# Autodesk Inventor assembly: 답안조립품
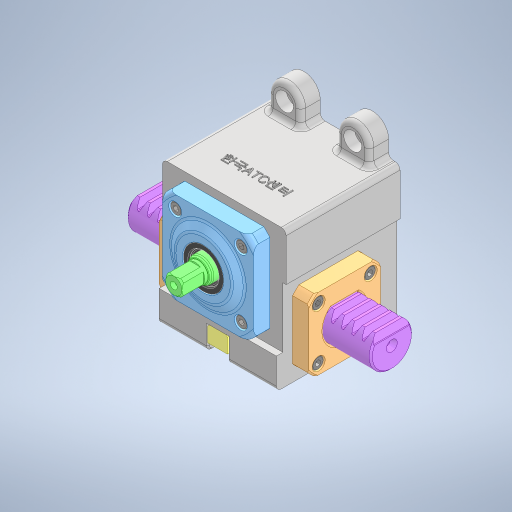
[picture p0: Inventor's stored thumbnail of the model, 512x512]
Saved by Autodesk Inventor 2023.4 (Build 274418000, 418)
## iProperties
Created: 2024-11
Part Number: 답안조립품
Document SubType Name: Assembly
Designer: EDU
Author: EDU
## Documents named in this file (10)
- C:\Users\EDU\Desktop\741104V1015\답안조립품.iam
- C:\Users\EDU\Desktop\741104V1015\본체.ipt
- C:\Users\EDU\Desktop\741104V1015\깊음 홈 볼 베어링 6202\깊음 홈 볼 베어링 6202.ipt
- C:\Users\EDU\Desktop\741104V1015\피니언 축\피니언 축.ipt
- C:\Users\EDU\Desktop\741104V1015\커버\커버.ipt
- C:\Users\EDU\Desktop\741104V1015\오일 실 15 25 4\오일 실 15 25 4.ipt
- C:\Users\EDU\Desktop\741104V1015\수지 부시\수지 부시.ipt
- C:\Users\EDU\Desktop\741104V1015\래크\래크.ipt
- C:\Users\EDU\Desktop\741104V1015\스톱퍼\스톱퍼.ipt
- C:\Users\EDU\Desktop\741104V1015\육각 소켓 머리 볼트 M4x10\육각 소켓 머리 볼트 M4x10.ipt
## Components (1 placed, 1 different names)
1. 피니언 축:1 — 각도:1
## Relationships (1: Angle 1)
- 각도:1 [Angle]: 피니언 축:1
